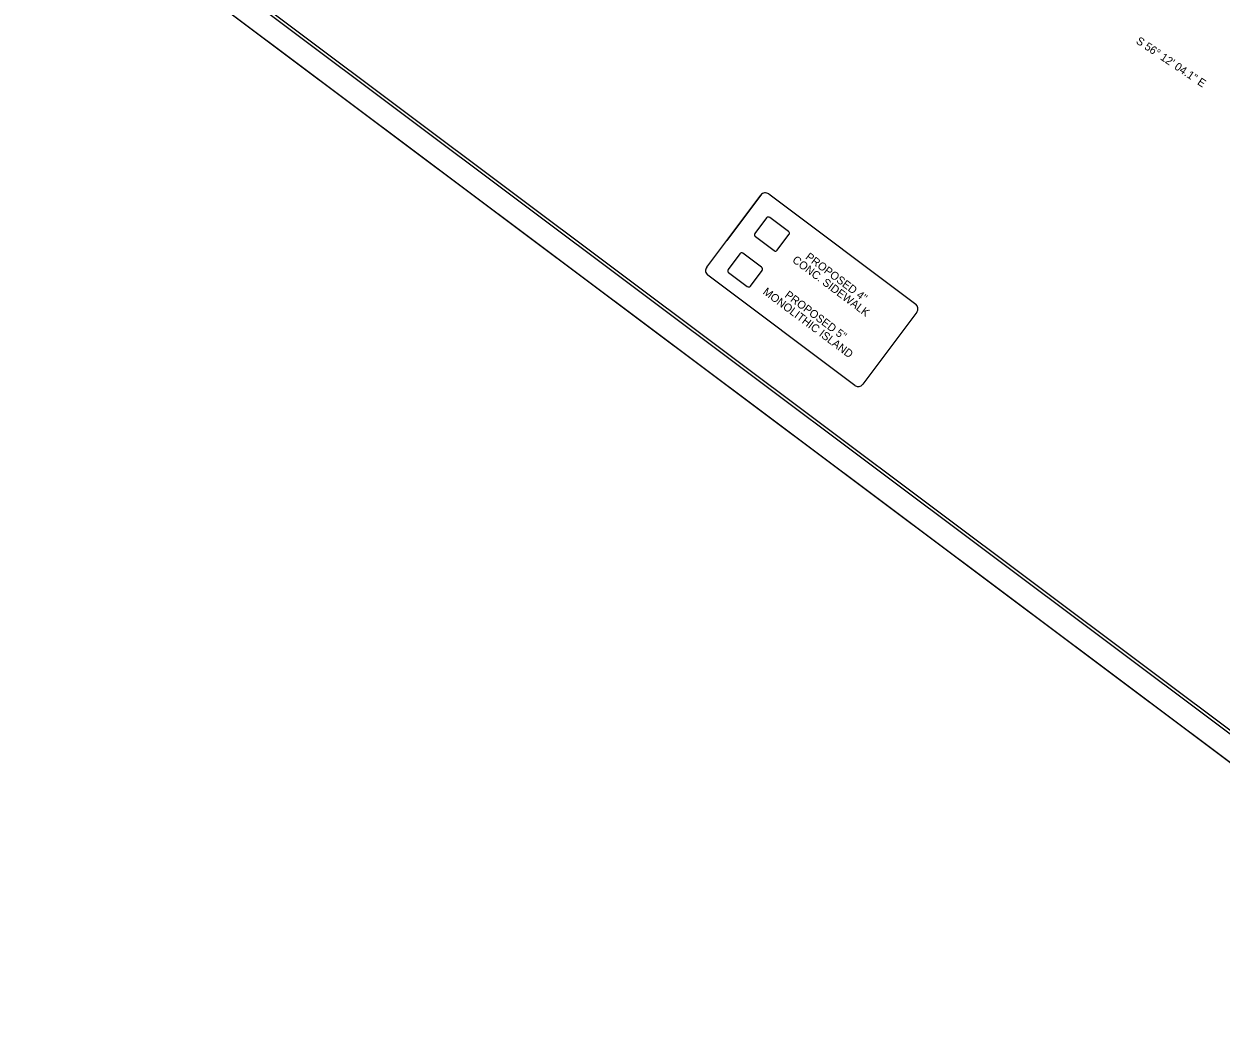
# Model space of a CAD drawing. Extents: x 928111 to 937215, y 684180 to 686530.
# Drawn here: x 930190 to 931236, y 684180 to 685045 of the extents above; entities that cross this region are included whole.
import ezdxf

# ---------------------------------------------------------------- set-up
doc = ezdxf.new("R2010")
doc.units = 0
for name, color, linetype in [('Exist Horizontal Alignment Direction Label', 7, 'Continuous'), ('Old_Level_2', 7, 'Continuous'), ('Prop DSN Text', 7, 'Continuous'), ('Sheet Cutting Line CELL', 7, 'Continuous'), ('Sheet Plan CELL', 7, 'Continuous'), ('Sheet Plan Layout CELL', 7, 'Continuous'), ('Sheet Plot Border Inside CELL', 7, 'Continuous'), ('Sheet Plot Border Outside CELL', 7, 'Continuous')]:
    doc.layers.add(name, color=color, linetype=linetype)

msp = doc.modelspace()

# ---------------------------------------------------------------- linework, layer by layer
at = {"layer": 'Old_Level_2'}
for p, q in [((930839.1, 684875.2), (930828.9, 684861.6)), ((930858.2, 684863.4), (930841.9, 684875.6)), ((930829.3, 684858.8), (930845.6, 684846.6)), ((930848.4, 684847), (930858.6, 684860.6)), ((930815.6, 684843.9), (930805.4, 684830.2)), ((930834.7, 684832.1), (930818.4, 684844.3)), ((930805.8, 684827.4), (930822.1, 684815.2)), ((930824.9, 684815.6), (930835.1, 684829.3))]:
    msp.add_line(p, q, dxfattribs=at)
for centre, start, end in [((930840.7, 684874), 53.1562, 143.1562), ((930830.5, 684860.4), 143.1562, 233.1562), ((930857, 684861.8), 323.1562, 53.1562), ((930817.2, 684842.7), 53.1562, 143.1562), ((930846.8, 684848.2), 233.1562, 323.1562), ((930807, 684829), 143.1562, 233.1562), ((930833.5, 684830.5), 323.1562, 53.1562), ((930823.3, 684816.8), 233.1562, 323.1562)]:
    msp.add_arc(centre, 2, start, end, dxfattribs=at)
at = {"layer": 'Prop DSN Text'}
for p, q in [((930786.7, 684832.1), (930833.9, 684895.1)), ((930833.9, 684895.1), (930804.2, 684855.5)), ((930840.9, 684896.1), (930969.4, 684799.8)), ((930916.3, 684728.8), (930787.7, 684825.1)), ((930970.4, 684792.8), (930923.3, 684729.8)), ((930970.4, 684792.8), (930940.8, 684753.2))]:
    msp.add_line(p, q, dxfattribs=at)
for centre, start, end in [((930837.9, 684892.1), 53.1562, 143.1562), ((930790.7, 684829.1), 143.1562, 233.1562), ((930966.4, 684795.8), 323.1562, 53.1562), ((930919.3, 684732.8), 233.1562, 323.1562)]:
    msp.add_arc(centre, 5, start, end, dxfattribs=at)
at = {"layer": 'Sheet Cutting Line CELL'}
msp.add_line((930189.7, 685189.6), (931537, 684180.1), dxfattribs=at)
at = {"layer": 'Sheet Plan CELL'}
msp.add_lwpolyline([(932166.5, 685048.6), (930966.1, 685948.1), (930336.5, 685107.8), (931536.9, 684208.3)], close=True, dxfattribs=at)
at = {"layer": 'Sheet Plan Layout CELL'}
msp.add_lwpolyline([(930966.1, 685948.1), (930336.5, 685107.8), (931536.9, 684208.3), (932039.7, 684879.4), (931848.2, 685022.8), (931975, 685192.1)], close=True, dxfattribs=at)
at = {"layer": 'Sheet Plot Border Inside CELL'}
msp.add_lwpolyline([(930212.1, 685197.8), (931545.4, 684198.8), (932178, 685043.1), (930844.7, 686042.1)], close=True, dxfattribs=at)
at = {"layer": 'Sheet Plot Border Outside CELL'}
msp.add_lwpolyline([(930189.7, 685189.6), (931537, 684180.1), (932193.6, 685056.4), (930846.3, 686065.9)], close=True, dxfattribs=at)

# ---------------------------------------------------------------- texts
at = {"layer": 'Exist Horizontal Alignment Direction Label'}
msp.add_text('S 56%%d 12\' 04.1" E', height=7, rotation=326.2011, dxfattribs=at).set_placement((931161.4, 685028.3))
at = {"layer": 'Prop DSN Text'}
for s, p in [('CONC. SIDEWALK', (930860.9, 684837.1)), ('PROPOSED 4"', (930872.4, 684839.9)), ('MONOLITHIC ISLAND', (930835.2, 684809.3)), ('PROPOSED 5"', (930854.3, 684806.5))]:
    msp.add_text(s, height=7, rotation=323.1562, dxfattribs=at).set_placement(p)

doc.saveas('drawing.dxf')
